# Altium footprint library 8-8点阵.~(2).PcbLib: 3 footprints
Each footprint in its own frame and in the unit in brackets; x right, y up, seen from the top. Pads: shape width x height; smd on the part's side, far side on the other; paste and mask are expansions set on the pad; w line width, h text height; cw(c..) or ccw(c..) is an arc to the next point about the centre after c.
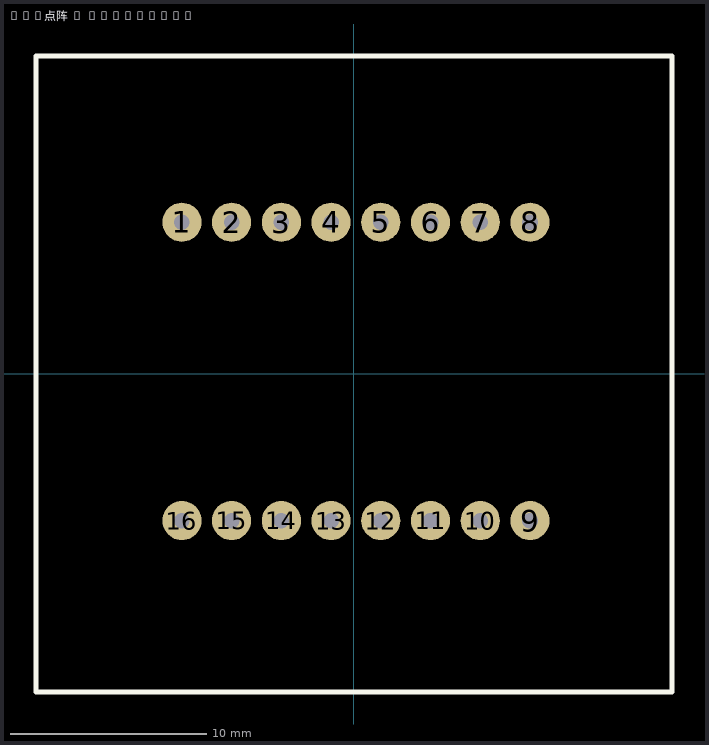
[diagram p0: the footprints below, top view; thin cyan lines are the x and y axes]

## 8-8点阵 [mm]

## 8-8点阵 - duplicate [mm]
pads (16):
  round 2 hole 0.8: 1(-8.78,7.74) 2(-6.24,7.74) 3(-3.7,7.74) 4(-1.16,7.74) 5(1.38,7.74) 6(3.92,7.74) 7(6.46,7.74) 8(9,7.74) 9(9,-7.5) 10(6.46,-7.5) 11(3.92,-7.5) 12(1.38,-7.5) 13(-1.16,-7.5) 14(-3.7,-7.5) 15(-6.24,-7.5) 16(-8.78,-7.5)
Top Overlay:
  lines w0.254: -16.24,-16.26 -16.24,16.24 16.26,16.24 16.26,-16.26 -16.24,-16.26

## PCBComponent_1 [mm]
